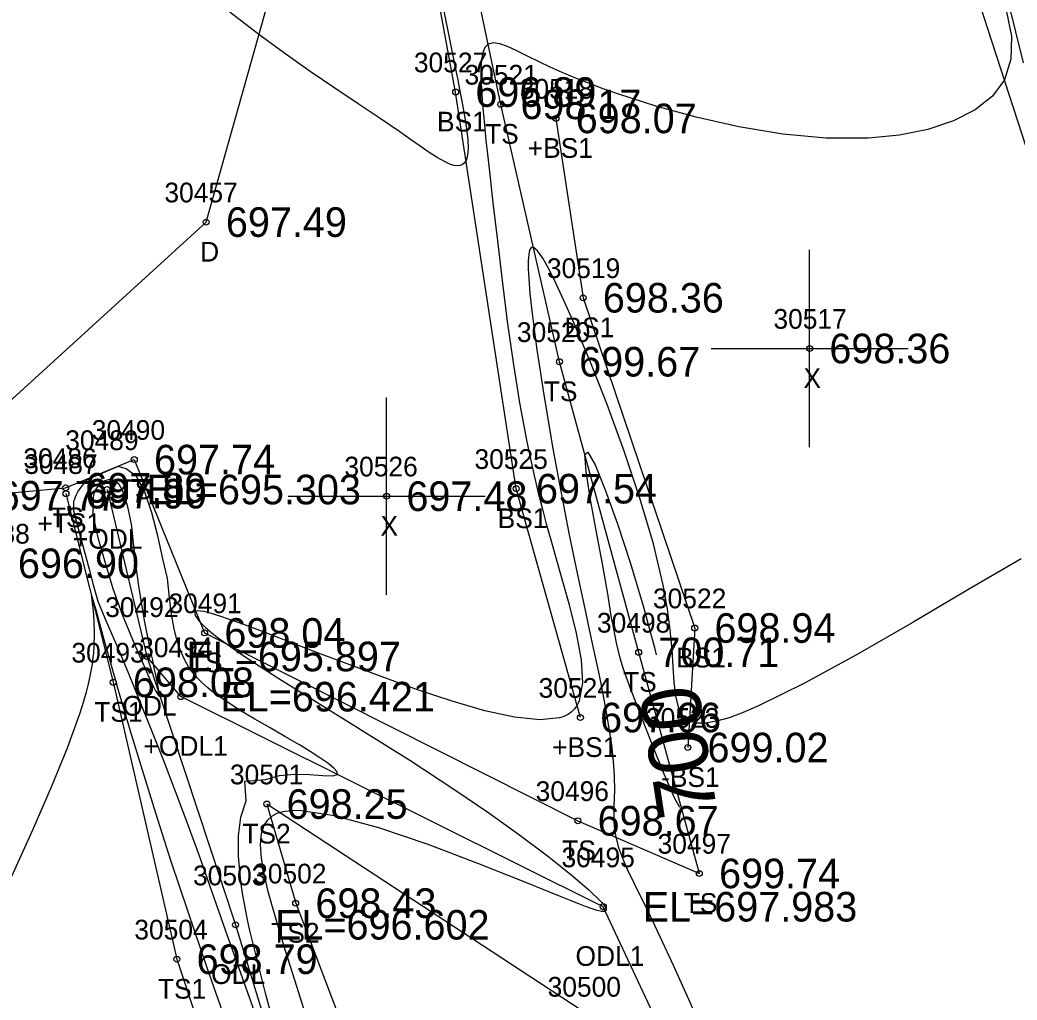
# Model space of a CAD drawing. Extents: x 1376587 to 1378239, y 1000335 to 1003031.
# Drawn here: x 1377533.1 to 1377583.6, y 1001619.2 to 1001668.9 of the extents above; entities that cross this region are included whole.
import ezdxf

# ---------------------------------------------------------------- set-up
doc = ezdxf.new("R2010")
doc.units = 0
for name, color, linetype in [('RD_DTM_BkLn2', 7, 'Continuous'), ('RD_DTM_BkLn_txCode', 7, 'Continuous'), ('RD_DTM_Major1', 7, 'Continuous'), ('RD_DTM_Major1_Lbl', 7, 'Continuous'), ('RD_DTM_Minor1', 7, 'Continuous'), ('RD_EX_Driveway', 7, 'Continuous'), ('RD_EX_Driveway_txCode', 7, 'Continuous'), ('RD_EX_H2O', 7, 'Continuous'), ('RD_EX_H2O_txCode', 7, 'Continuous'), ('RD_EX_Misc', 7, 'Continuous'), ('RD_EX_Misc_txCode', 7, 'Continuous'), ('RD_EX_TX_Driveway_ELEV', 7, 'Continuous'), ('RD_EX_TX_H2O_ELEV', 7, 'Continuous'), ('RD_EX_TX_Misc_ELEV', 7, 'Continuous'), ('RD_SMD_Locator', 7, 'Continuous')]:
    doc.layers.add(name, color=color, linetype=linetype)

msp = doc.modelspace()

# ---------------------------------------------------------------- linework, layer by layer
at = {"layer": 'RD_DTM_BkLn2'}
for points in [[(1377601.37, 1001619.875), (1377588.214, 1001649.787), (1377579.549, 1001676.429), (1377562.77, 1001744.864), (1377568.727, 1001756.063), (1377573.107, 1001760.313), (1377597.153, 1001755.06), (1377597.446, 1001756.515), (1377591.822, 1001759.637), (1377580.248, 1001777.496), (1377601.753, 1001798.682)], [(1377470.062, 1001604.722), (1377506.202, 1001626.069), (1377530.935, 1001644.783), (1377535.381, 1001645.184), (1377538.863, 1001646.614), (1377542.43, 1001637.827), (1377561.355, 1001628.305), (1377567.514, 1001625.634), (1377564.438, 1001636.843), (1377560.42, 1001651.576), (1377557.443, 1001664.625), (1377552.245, 1001689.355)], [(1377561.481, 1001633.538), (1377558.23, 1001645.14), (1377555.156, 1001665.248), (1377550.856, 1001688.627)], [(1377560.243, 1001663.912), (1377561.619, 1001654.818), (1377567.278, 1001638.076), (1377566.927, 1001632.018)], [(1377535.4, 1001644.887), (1377537.794, 1001635.323), (1377541.022, 1001621.285), (1377550.163, 1001593.701)], [(1377562.017, 1001618.386), (1377545.585, 1001629.152), (1377547.046, 1001624.126), (1377558.817, 1001593.153)]]:
    msp.add_lwpolyline(points, dxfattribs=at)
at = {"layer": 'RD_DTM_Major1'}
for points in [[(1377563.049, 1001638.699), (1377562.875, 1001639.804), (1377562.597, 1001641.323), (1377562.277, 1001643.022), (1377561.979, 1001644.669), (1377561.767, 1001646.03), (1377561.703, 1001646.872), (1377561.86, 1001646.995), (1377562.226, 1001646.345), (1377562.743, 1001645.08), (1377563.358, 1001643.362), (1377564.015, 1001641.349), (1377564.658, 1001639.203), (1377564.955, 1001638.138), (1377565.236, 1001637.086), (1377565.331, 1001636.712)], [(1377566.52, 1001628.969), (1377566.274, 1001629.432), (1377565.733, 1001630.659), (1377565.131, 1001632.137), (1377564.539, 1001633.658), (1377564.03, 1001635.012), (1377563.675, 1001635.99), (1377563.504, 1001636.544), (1377563.39, 1001636.963), (1377563.31, 1001637.318), (1377563.242, 1001637.678), (1377563.163, 1001638.115), (1377563.049, 1001638.699)]]:
    msp.add_lwpolyline(points, dxfattribs=at)
at = {"layer": 'RD_DTM_Minor1'}
for points in [[(1377554.385, 1001670.211), (1377555.017, 1001667.082), (1377555.103, 1001666.657), (1377555.185, 1001666.249), (1377555.264, 1001665.858), (1377555.407, 1001665.13), (1377555.471, 1001664.792), (1377555.606, 1001664.042), (1377555.706, 1001663.392), (1377555.769, 1001662.843), (1377555.789, 1001662.39), (1377555.763, 1001662.034), (1377555.687, 1001661.773), (1377555.609, 1001661.652), (1377555.508, 1001661.569), (1377555.387, 1001661.521), (1377555.245, 1001661.509), (1377555.084, 1001661.529), (1377554.904, 1001661.58), (1377554.585, 1001661.721), (1377554.221, 1001661.926), (1377553.814, 1001662.187), (1377553.362, 1001662.496), (1377552.865, 1001662.845), (1377552.323, 1001663.224), (1377551.323, 1001663.905), (1377550.218, 1001664.645), (1377549.03, 1001665.442), (1377547.78, 1001666.294), (1377546.49, 1001667.201), (1377545.182, 1001668.159), (1377543.635, 1001669.355)], [(1377583.159, 1001669.879), (1377583.934, 1001666.729)], [(1377583.062, 1001669.402), (1377583.338, 1001668.074), (1377583.308, 1001666.909), (1377582.982, 1001665.875), (1377582.376, 1001665.047), (1377581.502, 1001664.35), (1377580.398, 1001663.786), (1377579.103, 1001663.356), (1377577.657, 1001663.064), (1377576.096, 1001662.91), (1377573.951, 1001662.915), (1377571.739, 1001663.12), (1377569.521, 1001663.484), (1377567.355, 1001663.968), (1377565.304, 1001664.532), (1377563.426, 1001665.134), (1377562.638, 1001665.413), (1377561.898, 1001665.691), (1377561.205, 1001665.967), (1377560.557, 1001666.24), (1377559.954, 1001666.509), (1377559.395, 1001666.773), (1377558.799, 1001667.068), (1377558.265, 1001667.335), (1377557.794, 1001667.55), (1377557.39, 1001667.694), (1377557.058, 1001667.744), (1377556.801, 1001667.68), (1377556.637, 1001667.514), (1377556.527, 1001667.25), (1377556.463, 1001666.898), (1377556.438, 1001666.468), (1377556.442, 1001665.969), (1377556.469, 1001665.41), (1377556.525, 1001664.619), (1377556.601, 1001663.751), (1377556.695, 1001662.813), (1377556.804, 1001661.81), (1377556.923, 1001660.748), (1377557.05, 1001659.634), (1377557.272, 1001657.704), (1377557.513, 1001655.686), (1377557.777, 1001653.619), (1377558.071, 1001651.541), (1377558.4, 1001649.491), (1377558.768, 1001647.507), (1377558.947, 1001646.653), (1377559.135, 1001645.816), (1377559.332, 1001644.991), (1377559.537, 1001644.175), (1377559.752, 1001643.362), (1377559.976, 1001642.549), (1377560.441, 1001640.92), (1377560.888, 1001639.326), (1377561.264, 1001637.822), (1377561.513, 1001636.462), (1377561.584, 1001635.3), (1377561.421, 1001634.39), (1377561.371, 1001634.274), (1377561.315, 1001634.166), (1377561.25, 1001634.066), (1377561.179, 1001633.973), (1377561.1, 1001633.887), (1377561.013, 1001633.808), (1377560.93, 1001633.746), (1377560.842, 1001633.69), (1377560.748, 1001633.639), (1377560.647, 1001633.593), (1377560.54, 1001633.553), (1377560.427, 1001633.518), (1377559.421, 1001633.416), (1377558.14, 1001633.552), (1377556.642, 1001633.882), (1377554.985, 1001634.362), (1377553.226, 1001634.949), (1377551.423, 1001635.597), (1377549.791, 1001636.206), (1377548.21, 1001636.807), (1377546.721, 1001637.378), (1377545.364, 1001637.894), (1377544.179, 1001638.334), (1377543.207, 1001638.674), (1377542.903, 1001638.772), (1377542.637, 1001638.85), (1377542.411, 1001638.906), (1377542.226, 1001638.938), (1377542.083, 1001638.944), (1377541.986, 1001638.922), (1377541.936, 1001638.874), (1377541.927, 1001638.801), (1377541.957, 1001638.704), (1377542.026, 1001638.585), (1377542.134, 1001638.446), (1377542.281, 1001638.287), (1377542.339, 1001638.229), (1377542.401, 1001638.17), (1377542.468, 1001638.108), (1377542.539, 1001638.045), (1377542.614, 1001637.979), (1377542.694, 1001637.912), (1377542.751, 1001637.864), (1377542.811, 1001637.815), (1377542.873, 1001637.766), (1377543.003, 1001637.663), (1377543.071, 1001637.611), (1377544.426, 1001636.655), (1377546.192, 1001635.514), (1377548.257, 1001634.226), (1377550.507, 1001632.831), (1377552.832, 1001631.369), (1377555.118, 1001629.88), (1377556.833, 1001628.708), (1377558.41, 1001627.58), (1377559.809, 1001626.53), (1377560.988, 1001625.595), (1377561.905, 1001624.81), (1377562.517, 1001624.21), (1377562.565, 1001624.155), (1377562.609, 1001624.104), (1377562.649, 1001624.055), (1377562.683, 1001624.009), (1377562.713, 1001623.966), (1377562.739, 1001623.926), (1377562.767, 1001623.873), (1377562.785, 1001623.827), (1377562.793, 1001623.788), (1377562.79, 1001623.756), (1377562.776, 1001623.731), (1377562.751, 1001623.713), (1377562.724, 1001623.704), (1377562.689, 1001623.699), (1377562.648, 1001623.699), (1377562.6, 1001623.703), (1377562.544, 1001623.711), (1377562.483, 1001623.724), (1377562.282, 1001623.777), (1377562.035, 1001623.857), (1377561.741, 1001623.962), (1377561.403, 1001624.09), (1377561.022, 1001624.24), (1377560.599, 1001624.41), (1377558.635, 1001625.207), (1377556.286, 1001626.143), (1377553.762, 1001627.096), (1377551.27, 1001627.942), (1377549.019, 1001628.559), (1377547.218, 1001628.824), (1377546.782, 1001628.816), (1377546.406, 1001628.763), (1377546.088, 1001628.665), (1377545.826, 1001628.524), (1377545.616, 1001628.339), (1377545.456, 1001628.111), (1377545.295, 1001627.651), (1377545.245, 1001627.084), (1377545.292, 1001626.414), (1377545.424, 1001625.648), (1377545.625, 1001624.79), (1377545.882, 1001623.844), (1377546.433, 1001621.994), (1377547.083, 1001619.92), (1377547.8, 1001617.65)], [(1377583.827, 1001641.586), (1377581.131, 1001640.007), (1377578.299, 1001638.342), (1377575.484, 1001636.721), (1377572.84, 1001635.274), (1377570.519, 1001634.13), (1377569.73, 1001633.793), (1377569.017, 1001633.529), (1377568.385, 1001633.346), (1377567.836, 1001633.252), (1377567.375, 1001633.252), (1377567.004, 1001633.355), (1377566.668, 1001633.634), (1377566.448, 1001634.066), (1377566.315, 1001634.635), (1377566.237, 1001635.324), (1377566.185, 1001636.116), (1377566.128, 1001636.994), (1377566.087, 1001637.476), (1377566.036, 1001637.977), (1377565.972, 1001638.497), (1377565.895, 1001639.037), (1377565.802, 1001639.596), (1377565.693, 1001640.175), (1377565.182, 1001642.339), (1377564.502, 1001644.66), (1377563.704, 1001647.046), (1377562.837, 1001649.403), (1377561.952, 1001651.639), (1377561.099, 1001653.662), (1377560.662, 1001654.649), (1377560.256, 1001655.52), (1377559.89, 1001656.252), (1377559.569, 1001656.821), (1377559.302, 1001657.206), (1377559.095, 1001657.382), (1377558.984, 1001657.368), (1377558.906, 1001657.239), (1377558.859, 1001657.006), (1377558.838, 1001656.683), (1377558.84, 1001656.281), (1377558.863, 1001655.812), (1377558.924, 1001655.036), (1377559.016, 1001654.162), (1377559.135, 1001653.206), (1377559.276, 1001652.183), (1377559.435, 1001651.111), (1377559.609, 1001650.005), (1377559.841, 1001648.592), (1377560.089, 1001647.162), (1377560.348, 1001645.727), (1377560.617, 1001644.297), (1377560.894, 1001642.885), (1377561.176, 1001641.502), (1377561.431, 1001640.297), (1377561.684, 1001639.127), (1377561.932, 1001637.993), (1377562.17, 1001636.898), (1377562.393, 1001635.843), (1377562.598, 1001634.832), (1377562.776, 1001633.891), (1377562.929, 1001632.993), (1377563.053, 1001632.139), (1377563.143, 1001631.331), (1377563.197, 1001630.568), (1377563.211, 1001629.852), (1377563.2, 1001629.447), (1377563.183, 1001629.053), (1377563.172, 1001628.664), (1377563.177, 1001628.275), (1377563.208, 1001627.88), (1377563.276, 1001627.472), (1377563.419, 1001626.951), (1377563.622, 1001626.4), (1377563.877, 1001625.817), (1377564.172, 1001625.197), (1377564.498, 1001624.537), (1377564.846, 1001623.835), (1377565.512, 1001622.438), (1377566.2, 1001620.944), (1377566.892, 1001619.407), (1377567.57, 1001617.885)], [(1377538.443, 1001646.153), (1377538.045, 1001646.269), (1377536.815, 1001645.743), (1377536.405, 1001645.546), (1377536.103, 1001645.154), (1377536.035, 1001645.043), (1377535.973, 1001644.932), (1377535.918, 1001644.821), (1377535.869, 1001644.709), (1377535.826, 1001644.596), (1377535.788, 1001644.483), (1377535.778, 1001644.015), (1377536.069, 1001642.928), (1377536.568, 1001641.064), (1377536.785, 1001640.259), (1377537.014, 1001639.434), (1377537.377, 1001638.576), (1377538.157, 1001636.743), (1377538.567, 1001635.769), (1377539.149, 1001634.357), (1377539.741, 1001632.885), (1377540.339, 1001631.363), (1377540.937, 1001629.806), (1377541.529, 1001628.226), (1377542.111, 1001626.636), (1377542.457, 1001625.672), (1377542.798, 1001624.709), (1377543.477, 1001622.775), (1377544.161, 1001620.824), (1377544.683, 1001619.353), (1377545.191, 1001617.949)], [(1377545.751, 1001618.686), (1377545.541, 1001619.488), (1377545.329, 1001620.301), (1377545.119, 1001621.118), (1377544.917, 1001621.932), (1377544.728, 1001622.738), (1377544.628, 1001623.192), (1377544.534, 1001623.642), (1377544.449, 1001624.088), (1377544.372, 1001624.529), (1377544.304, 1001624.967), (1377544.247, 1001625.401), (1377544.154, 1001626.503), (1377544.155, 1001627.547), (1377544.273, 1001628.494), (1377544.529, 1001629.31), (1377544.469, 1001630.309), (1377545.534, 1001630.396), (1377546.221, 1001630.599), (1377546.986, 1001630.663), (1377547.747, 1001630.643), (1377548.419, 1001630.596), (1377548.92, 1001630.579), (1377549.166, 1001630.649), (1377549.147, 1001630.779), (1377548.976, 1001630.972), (1377548.676, 1001631.217), (1377548.269, 1001631.502), (1377547.78, 1001631.817), (1377547.232, 1001632.15), (1377546.503, 1001632.574), (1377545.744, 1001633.007), (1377544.979, 1001633.447), (1377544.234, 1001633.894), (1377543.532, 1001634.344), (1377542.898, 1001634.798), (1377542.591, 1001635.045), (1377542.31, 1001635.297), (1377542.055, 1001635.556), (1377541.825, 1001635.825), (1377541.62, 1001636.109), (1377541.438, 1001636.41), (1377541.215, 1001636.882), (1377541.032, 1001637.417), (1377540.882, 1001638.035), (1377540.757, 1001638.756), (1377540.649, 1001639.599), (1377540.553, 1001640.584), (1377540.308, 1001641.59), (1377540.049, 1001642.745), (1377539.754, 1001643.915), (1377539.402, 1001644.964), (1377538.972, 1001645.755), (1377538.443, 1001646.153)], [(1377537.876, 1001645.531), (1377537.714, 1001645.588), (1377537.54, 1001645.592), (1377537.363, 1001645.545), (1377537.193, 1001645.449), (1377537.041, 1001645.306), (1377536.915, 1001645.12), (1377536.886, 1001645.062), (1377536.861, 1001645), (1377536.837, 1001644.934), (1377536.817, 1001644.866), (1377536.799, 1001644.795), (1377536.783, 1001644.721), (1377536.76, 1001643.819), (1377537.008, 1001642.671), (1377537.39, 1001641.383), (1377537.777, 1001640.075), (1377538.254, 1001638.757), (1377538.77, 1001637.502), (1377538.892, 1001637.214), (1377539.011, 1001636.936), (1377539.126, 1001636.669), (1377539.238, 1001636.414), (1377539.345, 1001636.171), (1377539.448, 1001635.942), (1377539.64, 1001635.521), (1377539.807, 1001635.169), (1377539.946, 1001634.896), (1377540.054, 1001634.71), (1377540.126, 1001634.623), (1377540.161, 1001634.646), (1377540.108, 1001634.91), (1377540.055, 1001635.175), (1377540.002, 1001635.439), (1377539.949, 1001635.704), (1377539.896, 1001635.968), (1377539.843, 1001636.233), (1377539.796, 1001636.44), (1377539.75, 1001636.65), (1377539.703, 1001636.863), (1377539.611, 1001637.298), (1377539.566, 1001637.522), (1377539.403, 1001638.372), (1377539.246, 1001639.274), (1377539.099, 1001640.219), (1377538.964, 1001641.201), (1377538.844, 1001642.211), (1377538.743, 1001643.244), (1377538.637, 1001643.744), (1377538.529, 1001644.227), (1377538.409, 1001644.67), (1377538.267, 1001645.05), (1377538.093, 1001645.345), (1377537.876, 1001645.531)], [(1377544.155, 1001616.316), (1377542.56, 1001620.84), (1377541.591, 1001623.681), (1377540.724, 1001626.295), (1377539.952, 1001628.69), (1377539.271, 1001630.872), (1377538.672, 1001632.847), (1377538.151, 1001634.622), (1377538.034, 1001635.028), (1377537.921, 1001635.422), (1377537.812, 1001635.804), (1377537.707, 1001636.175), (1377537.606, 1001636.535), (1377537.508, 1001636.884), (1377537.292, 1001637.664), (1377537.102, 1001638.356), (1377536.941, 1001638.935), (1377536.815, 1001639.375), (1377536.73, 1001639.651), (1377536.689, 1001639.737), (1377536.693, 1001639.629), (1377536.725, 1001639.355), (1377536.77, 1001638.942), (1377536.81, 1001638.418), (1377536.831, 1001637.81), (1377536.816, 1001637.145), (1377536.812, 1001637.074), (1377536.807, 1001637.002), (1377536.801, 1001636.931), (1377536.789, 1001636.786), (1377536.781, 1001636.713), (1377536.724, 1001636.261), (1377536.643, 1001635.797), (1377536.54, 1001635.317), (1377536.415, 1001634.82), (1377536.268, 1001634.304), (1377536.099, 1001633.766), (1377535.461, 1001631.992), (1377534.654, 1001630.01), (1377533.706, 1001627.834), (1377532.643, 1001625.475)]]:
    msp.add_lwpolyline(points, dxfattribs=at)
at = {"layer": 'RD_EX_Driveway'}
msp.add_lwpolyline([(1377447.053, 1001595.812), (1377448.223, 1001596.066), (1377484.138, 1001614.601), (1377514.751, 1001633.355), (1377542.508, 1001658.654), (1377546.462, 1001672.709), (1377548.691, 1001700.514), (1377552.886, 1001726.646), (1377558.243, 1001740.288), (1377561.82, 1001749.958), (1377574.839, 1001777.427), (1377592.976, 1001805.197), (1377604.946, 1001815.767)], dxfattribs=at)
at = {"layer": 'RD_EX_H2O'}
for points in [[(1377537.481, 1001645.097), (1377539.504, 1001636.633), (1377543.999, 1001623.03), (1377552.851, 1001594.036)], [(1377568.307, 1001611.817), (1377562.642, 1001623.947), (1377541.228, 1001634.596), (1377539.504, 1001636.633)]]:
    msp.add_lwpolyline(points, dxfattribs=at)
at = {"layer": 'RD_EX_Misc'}
for p, q in [((1377573.104, 1001647.247), (1377573.104, 1001657.247)), ((1377568.104, 1001652.247), (1377578.104, 1001652.247)), ((1377551.659, 1001639.76), (1377551.659, 1001649.76)), ((1377546.659, 1001644.76), (1377556.659, 1001644.76))]:
    msp.add_line(p, q, dxfattribs=at)
at = {"layer": 'RD_SMD_Locator'}
for centre in [(1377555.156, 1001665.248), (1377557.443, 1001664.625), (1377560.243, 1001663.912), (1377542.508, 1001658.654), (1377561.619, 1001654.818), (1377573.104, 1001652.247), (1377560.42, 1001651.576), (1377538.863, 1001646.614), (1377535.381, 1001645.184), (1377537.481, 1001645.097), (1377558.23, 1001645.14), (1377535.4, 1001644.887), (1377551.659, 1001644.76), (1377567.278, 1001638.076), (1377542.43, 1001637.827), (1377539.504, 1001636.633), (1377564.438, 1001636.843), (1377537.794, 1001635.323), (1377541.228, 1001634.596), (1377561.481, 1001633.538), (1377566.927, 1001632.018), (1377545.585, 1001629.152), (1377561.355, 1001628.305), (1377567.514, 1001625.634), (1377547.046, 1001624.126), (1377562.642, 1001623.947), (1377543.999, 1001623.03), (1377541.022, 1001621.285)]:
    msp.add_circle(centre, 0.15, dxfattribs=at)

# ---------------------------------------------------------------- texts
at = {"layer": 'RD_DTM_BkLn_txCode'}
for s, p in [('30527', (1377553.038, 1001666.248)), ('30521', (1377555.608, 1001665.625)), ('30518', (1377558.408, 1001664.912)), ('BS1', (1377554.211, 1001663.248)), ('TS', (1377556.648, 1001662.625)), ('+BS1', (1377558.81, 1001661.912)), ('30519', (1377559.784, 1001655.818)), ('BS1', (1377560.674, 1001652.818)), ('30520', (1377558.263, 1001652.576)), ('TS', (1377559.625, 1001649.576)), ('30490', (1377536.706, 1001647.614)), ('30486', (1377533.239, 1001646.184)), ('30487', (1377533.282, 1001645.887)), ('30525', (1377556.112, 1001646.14)), ('TS', (1377538.068, 1001644.614)), ('+TS1', (1377533.951, 1001642.887)), ('TS', (1377534.586, 1001643.184)), ('BS1', (1377557.285, 1001643.14)), ('30488', (1377529.846, 1001642.355)), ('30491', (1377540.595, 1001638.827)), ('30522', (1377565.16, 1001639.076)), ('30498', (1377562.32, 1001637.843)), ('30493', (1377535.676, 1001636.323)), ('TS', (1377541.635, 1001635.827)), ('BS1', (1377566.333, 1001636.076)), ('TS', (1377563.643, 1001634.843)), ('30524', (1377559.363, 1001634.538)), ('TS1', (1377536.833, 1001633.323)), ('30523', (1377564.809, 1001633.018)), ('+BS1', (1377560.048, 1001631.538)), ('30501', (1377543.711, 1001630.152)), ('-BS1', (1377565.573, 1001630.018)), ('30496', (1377559.213, 1001629.305)), ('TS2', (1377544.341, 1001627.152)), ('30497', (1377565.396, 1001626.634)), ('TS', (1377560.56, 1001626.305)), ('30502', (1377544.889, 1001625.126)), ('TS', (1377566.719, 1001623.634)), ('30504', (1377538.865, 1001622.285)), ('TS2', (1377545.802, 1001622.126)), ('TS1', (1377540.061, 1001619.285)), ('30500', (1377559.82, 1001619.386))]:
    msp.add_text(s, height=1, dxfattribs=at).set_placement(p)
at = {"layer": 'RD_DTM_Major1_Lbl'}
msp.add_text('700', height=3, rotation=98.7309, dxfattribs=at).set_placement((1377568.432, 1001628.706))
at = {"layer": 'RD_EX_Driveway_txCode'}
for s, p in [('30457', (1377540.39, 1001659.654)), ('D', (1377542.201, 1001656.654))]:
    msp.add_text(s, height=1, dxfattribs=at).set_placement(p)
at = {"layer": 'RD_EX_H2O_txCode'}
for s, p in [('30489', (1377535.363, 1001647.097)), ('+ODL', (1377535.749, 1001642.097)), ('30492', (1377537.386, 1001638.633)), ('30494', (1377539.11, 1001636.596)), ('ODL', (1377538.26, 1001633.633)), ('+ODL1', (1377539.33, 1001631.596)), ('30495', (1377560.524, 1001625.947)), ('30503', (1377541.842, 1001625.03)), ('ODL1', (1377561.233, 1001620.947)), ('ODL', (1377542.755, 1001620.03))]:
    msp.add_text(s, height=1, dxfattribs=at).set_placement(p)
at = {"layer": 'RD_EX_Misc_txCode'}
for s, p in [('30517', (1377571.269, 1001653.247)), ('X', (1377572.789, 1001650.247)), ('30526', (1377549.517, 1001645.76)), ('X', (1377551.344, 1001642.76))]:
    msp.add_text(s, height=1, dxfattribs=at).set_placement(p)
at = {"layer": 'RD_EX_TX_Driveway_ELEV'}
msp.add_text('697.49', height=1.5, dxfattribs=at).set_placement((1377543.508, 1001657.904))
at = {"layer": 'RD_EX_TX_H2O_ELEV'}
for s, p in [('EL=695.303', (1377539.481, 1001644.347)), ('EL=695.897', (1377541.504, 1001635.883)), ('EL=696.421', (1377543.228, 1001633.846)), ('EL=697.983', (1377564.642, 1001623.197)), ('EL=696.602', (1377545.999, 1001622.28))]:
    msp.add_text(s, height=1.5, dxfattribs=at).set_placement(p)
at = {"layer": 'RD_EX_TX_Misc_ELEV'}
for s, p in [('696.89', (1377556.156, 1001664.498)), ('698.17', (1377558.443, 1001663.875)), ('698.07', (1377561.243, 1001663.162)), ('698.36', (1377562.619, 1001654.068)), ('698.36', (1377574.104, 1001651.497)), ('699.67', (1377561.42, 1001650.826)), ('697.74', (1377539.863, 1001645.864)), ('697.89', (1377536.381, 1001644.434)), ('697.54', (1377559.23, 1001644.39)), ('697.77', (1377531.935, 1001644.033)), ('697.90', (1377536.4, 1001644.137)), ('697.48', (1377552.659, 1001644.01)), ('696.90', (1377532.964, 1001640.605)), ('698.94', (1377568.278, 1001637.326)), ('698.04', (1377543.43, 1001637.077)), ('700.71', (1377565.438, 1001636.093)), ('698.08', (1377538.794, 1001634.573)), ('697.96', (1377562.481, 1001632.788)), ('699.02', (1377567.927, 1001631.268)), ('698.25', (1377546.585, 1001628.402)), ('698.67', (1377562.355, 1001627.555)), ('699.74', (1377568.514, 1001624.884)), ('698.43', (1377548.046, 1001623.376)), ('698.79', (1377542.022, 1001620.535))]:
    msp.add_text(s, height=1.5, dxfattribs=at).set_placement(p)

doc.saveas('drawing.dxf')
